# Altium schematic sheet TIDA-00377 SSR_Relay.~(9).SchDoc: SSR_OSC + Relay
size 431 x 279 mm; Date: Not shown in title block; ApprovedBy: Not shown in title block; CheckedBy: Not shown in title block; Author: Not shown in title block; CompanyName: Not shown in title block; DrawnBy: Jarrod Krebs; Engineer: Not shown in title block; Organization: Not shown in title block; Address1: Not shown in title block; Address2: Not shown in title block; Address3: Not shown in title block; Address4: Not shown in title block; DocumentNumber: 1; Revision: Use project parameter SCH_Rev; SheetNumber: 2; SheetTotal: 3; PageSetup: Record=PageOptions¦CenterHorizontal=True¦CenterVertical=True¦PrintScale=0.62¦XCorrection=1.00¦YCorrection=1.00¦PrintKind=0¦BorderSize=5000000¦LeftOffset=0¦BottomOffset=0¦Orientation=2¦PaperLength=1000¦PaperWidth=1000¦Scale=100¦PaperSource=15¦PrintQuality=-3¦MediaType=1¦DitherType=10¦PrintScaleMode=1¦PaperKind=Letter¦PaperIndex=1
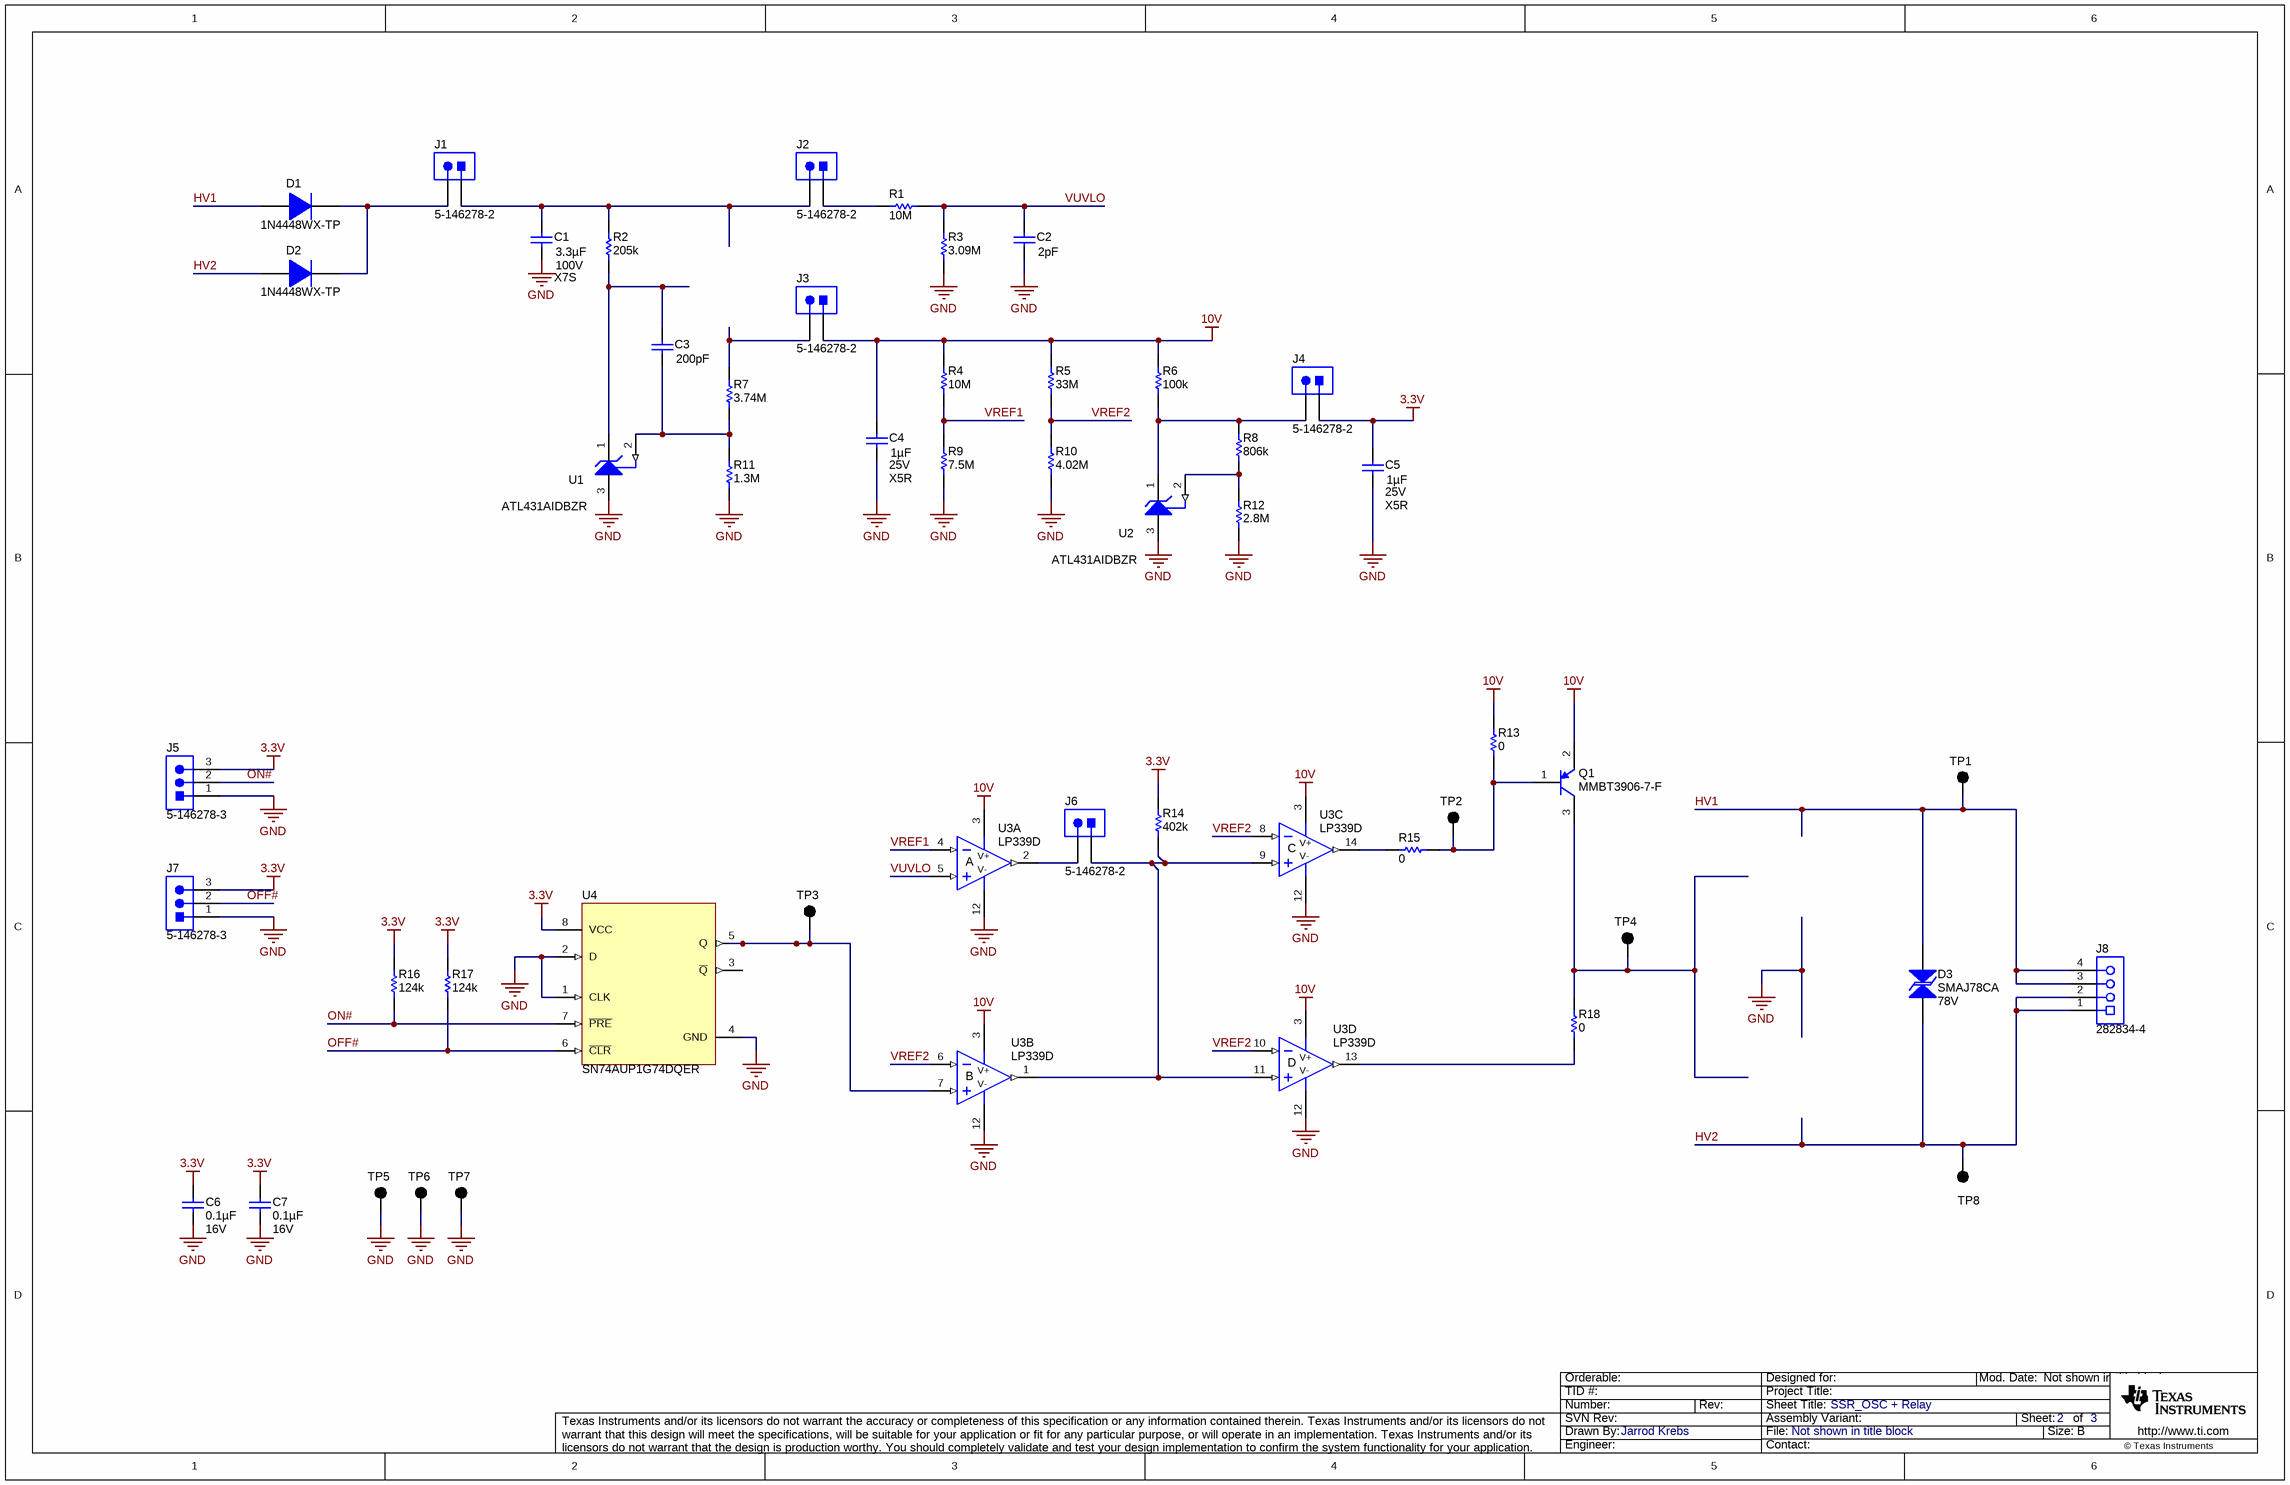
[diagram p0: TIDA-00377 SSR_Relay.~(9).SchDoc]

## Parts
C1  ValueDisplayed: 3.3µF  VDC_V: 100V  TempCo: X7S  [0603]  (hidden comment: GRM188R61E105KA12D)
C2  ValueDisplayed: 2pF  [0603]  (hidden comment: GRM188R61E105KA12D)
C3  ValueDisplayed: 200pF  [0603]  (hidden comment: GRM188R61E105KA12D)
C4  ValueDisplayed: 1µF  Value2: 25V  TempCo: X5R  [0603]  (hidden comment: GRM188R61E105KA12D)
C5  ValueDisplayed: 1µF  Value2: 25V  TempCo: X5R  [0603]  (hidden comment: GRM188R61E105KA12D)
C6  ValueDisplayed: 0.1µF  Value2: 16V  [0603]  (hidden comment: GRM188R71C104KA01D)
C7  ValueDisplayed: 0.1µF  Value2: 16V  [0603]  (hidden comment: GRM188R71C104KA01D)
D1  1N4448WX-TP  [sod-323]
D2  1N4448WX-TP  [sod-323]
D3  SMAJ78CA  value 78V  [SMA]
J1  5-146278-2  [TE_5-146278-2]
J2  5-146278-2  [TE_5-146278-2]
J3  5-146278-2  [TE_5-146278-2]
J4  5-146278-2  [TE_5-146278-2]
J5  5-146278-3  [TE_5-146278-3]
J6  5-146278-2  [TE_5-146278-2]
J7  5-146278-3  [TE_5-146278-3]
J8  282834-4  [TEC_282834-4]
Q1  MMBT3906-7-F  [SOT-23]
R1  ValueDisplayed: 10M  [0805_HV]  (hidden comment: CRCW08050000Z0EA)
R2  ValueDisplayed: 205k  [0805_HV]  (hidden comment: CRCW08050000Z0EA)
R3  ValueDisplayed: 3.09M  [0805_HV]  (hidden comment: CRCW08050000Z0EA)
R4  ValueDisplayed: 10M  [0805_HV]  (hidden comment: CRCW08050000Z0EA)
R5  ValueDisplayed: 33M  [0805_HV]  (hidden comment: CRCW08050000Z0EA)
R6  ValueDisplayed: 100k  [0805_HV]  (hidden comment: CRCW08050000Z0EA)
R7  ValueDisplayed: 3.74M  [0805_HV]  (hidden comment: CRCW08050000Z0EA)
R8  ValueDisplayed: 806k  [0805_HV]  (hidden comment: CRCW08050000Z0EA)
R9  ValueDisplayed: 7.5M  [0805_HV]  (hidden comment: CRCW08050000Z0EA)
R10  ValueDisplayed: 4.02M  [0805_HV]  (hidden comment: CRCW08050000Z0EA)
R11  ValueDisplayed: 1.3M  [0805_HV]  (hidden comment: CRCW08050000Z0EA)
R12  ValueDisplayed: 2.8M  [0805_HV]  (hidden comment: CRCW08050000Z0EA)
R13  ValueDisplayed: 0  [0805_HV]  (hidden comment: CRCW08050000Z0EA)
R14  ValueDisplayed: 402k  [0805_HV]  (hidden comment: CRCW08050000Z0EA)
R15  ValueDisplayed: 0  [0805_HV]  (hidden comment: CRCW08050000Z0EA)
R16  ValueDisplayed: 124k  [0402]  (hidden comment: CRCW0402100KJNED)
R17  ValueDisplayed: 124k  [0402]  (hidden comment: CRCW0402100KJNED)
R18  ValueDisplayed: 0  [0805_HV]  (hidden comment: CRCW08050000Z0EA)
TP1  5001  [Keystone5001]  (value not drawn)
TP2  5001  [Keystone5001]  (value not drawn)
TP3  5001  [Keystone5001]  (value not drawn)
TP4  5001  [Keystone5001]  (value not drawn)
TP5  5001  [Keystone5001]  (value not drawn)
TP6  5001  [Keystone5001]  (value not drawn)
TP7  5001  [Keystone5001]  (value not drawn)
TP8  5001  [Keystone5001]  (value not drawn)
U1  ATL431AIDBZR  [DBZ0003A_M]
U2  ATL431AIDBZR  [DBZ0003A_M]
U3  LP339D  [D0014A_N]  (parts A,B,C,D of 4)
U4  SN74AUP1G74DQER  [DQE0008A]

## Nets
3.3V: C5.2 C6.2 C7.2 J4.1 J5.3 J7.3 R14.1 R16.2 R17.2 U4.8(VCC)
10V: C4.2 J3.1 Q1.2(E) R4.1 R5.1 R6.1 R13.1 U3.3(V+)
GND: C1.1 C2.1 C4.1 C5.1 C6.1 C7.1 J5.1 J7.1 R3.2 R9.2 R10.2 R11.2 R12.2 TP5.1 TP6.1 TP7.1 U1.3(ANODE) U2.3(ANODE) U3.12(V-) U4.1(CLK) U4.2(D) U4.4(GND)
HV1: D1.2(A) D3.2 J8.3 J8.4 TP1.1
HV2: D2.2(A) D3.1 J8.1 J8.2 TP8.1
OFF#: J7.2 R17.1 U4.6(~{CLR})
ON#: J5.2 R16.1 U4.7(~{PRE})
VREF1: R4.2 R9.1 U3.4(-IN1)
VREF2: R5.2 R10.1 U3.6(-IN2) U3.8(-IN3) U3.10(-IN4)
VUVLO: C2.2 R1.2 R3.1 U3.5(+IN1)
NetC1_2: C1.2 J1.1 J2.2 R2.1
NetC3_1: C3.1 R7.2 R11.1 U1.2(REF)
NetC3_2: C3.2 R2.2 U1.1(CATHODE)
NetD1_1: D1.1(K) D2.1(K) J1.2
NetJ2_1: J2.1 R1.1
NetJ3_2: J3.2 R7.1
NetJ4_2: J4.2 R6.2 R8.1 U2.1(CATHODE)
NetJ6_1: J6.1 R14.2 U3.1(OUT2) U3.9(+IN3) U3.11(+IN4)
NetJ6_2: J6.2 U3.2(OUT1)
NetQ1_1: Q1.1(B) R13.2 R15.2 TP2.1
NetQ1_3: Q1.3(C) R18.2 TP4.1
NetR8_2: R8.2 R12.1 U2.2(REF)
NetR15_1: R15.1 U3.14(OUT3)
NetR18_1: R18.1 U3.13(OUT4)
NetTP3_1: TP3.1 U3.7(+IN2) U4.5(Q)

Not connected (* = marked no-connect by the designer): U4 3(~{Q})

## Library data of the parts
C1 = GRM188R61E105KA12D: CAP, CERM, 3.3 µF, 100 V, +/- 10%, X5R, 0603; Manufacturer: MuRata; Polarized: N; CompType: Capacitor; Value: 1uF; U/M: EA; Cap_F: 0.000001; Tolerance_%: 10; Value1: Unknown; TaMin_C: -55; TaMax_C: 85; AEC Category: Q200
C2 C3 = GRM188R61E105KA12D: CAP, CERM, 1 µF, 25 V, +/- 10%, X5R, 0603; Manufacturer: MuRata; Polarized: N; CompType: Capacitor; Value: 1uF; U/M: EA; Cap_F: 0.000001; Tolerance_%: 10; Value1: Unknown; VDC_V: 25; Value2: 25V; TaMin_C: -55; TaMax_C: 85; AEC Category: Q200
C4 C5 = GRM188R61E105KA12D: CAP, CERM, 1 µF, 25 V, +/- 10%, X5R, 0603; Manufacturer: MuRata; Polarized: N; CompType: Capacitor; Value: 1uF; U/M: EA; Cap_F: 0.000001; Tolerance_%: 10; Value1: Unknown; VDC_V: 25; TaMin_C: -55; TaMax_C: 85; AEC Category: Q200
C6 C7 = GRM188R71C104KA01D: CAP, CERM, 0.1 µF, 16 V, +/- 10%, X7R, 0603; Manufacturer: MuRata; Polarized: N; CompType: Capacitor; Value: 0.1uF; U/M: EA; Cap_F: 0.0000001; Tolerance_%: 10; Value1: Unknown; VDC_V: 16; TaMin_C: -55; TaMax_C: 125; AEC Category: Q200
D1 D2 = 1N4448WX-TP: Diode, Switching, 75 V, 0.25 A, SOD-323; Manufacturer: Micro Commercial Components; U/M: EA; Value: 75V; Value1: 0.25A; Io_A: 0.25; Vr_V: 75; TJmax_C: 150; AEC Category: Q101
D3 = SMAJ78CA: Diode, TVS, Bi, 78 V, 400 W, SMA; Manufacturer: Littelfuse; U/M: EA; Power_W: 400; Vr_V: 78; Value1: 400W; RJA_CperW: 120; AEC Category: Q101
J1-J4 J6 = 5-146278-2: Header, 100mil, 2x1, Tin, TH; Manufacturer: TE Connectivity; SymbolCreator: a0412235; U/M: EA
J5 J7 = 5-146278-3: Header, 100mil, 3x1, Tin, TH; Manufacturer: TE Connectivity; SymbolCreator: a0799628
J8 = 282834-4: Terminal Block, 100mil, 4X1 TH; Manufacturer: TE Connectivity; SymbolCreator: a0411947
Q1 = MMBT3906-7-F, Diodes Inc.: Transistor, PNP, 40 V, 0.2 A, SOT-23; CompType: BJT; PNP: 1; NPN: 0; Vceo_V: 40; Vcesat1_V: 0.25; Value: 40 V; IcRated_A: 0.2; Value1: 0.2 A; HfeMax: 400; TaMin_C: -55; TaMax_C: 150; U/M: EA; AEC Category: Q101
R1-R15 R18 = CRCW08050000Z0EA: RES, 0, 5%, 0.125 W, 0805; Manufacturer: Vishay-Dale; CompType: Resistor; Value: 0; Value_Code: 0000; Tolerance_%: 5; Power_W: 0.125; Value2: 0.125W; VDC_V: 150; TempCo: 200 ppm/C; EIA_Code: E24; U/M: EA; AEC Category: Q200
R16 R17 = CRCW0402100KJNED: RES, 100 k, 5%, 0.063 W, 0402; Manufacturer: Vishay-Dale; CompType: Resistor; Value: 100k; Res_ohm: 100000; Tolerance_%: 5; Power_W: 0.063; Value2: 0.063W; VDC_V: 50; TempCo: 200 ppm/C; EIA_Code: E24; U/M: EA; AEC Category: Q200
TP1-TP8 = 5001: Test Point, Miniature, Black, TH; Manufacturer: Keystone; CompType: Test Point Loop; U/M: EA
U1 U2 = ATL431AIDBZR: 2.5V Low Iq Adjustable Precision Shunt Regulator, DBZ0003A; Manufacturer: Texas Instruments; SymbolCreator: a0412235; CompType: IC; U/M: EA
U3 = LP339D: Quad, Low-Power, General Purpose Differential Comparator, D0014A; Manufacturer: Texas Instruments; SymbolCreator: Altium; CompType: OpAmp IC
U4 = SN74AUP1G74DQER: LOW-POWER SINGLE POSITIVE-EDGE-TRIGGERED D-TYPE FLIP-FLOP WITH CLEAR AND PRESET, DQE0008A; Manufacturer: Texas Instruments; SymbolCreator: a0799628; CompType: IC; U/M: EA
